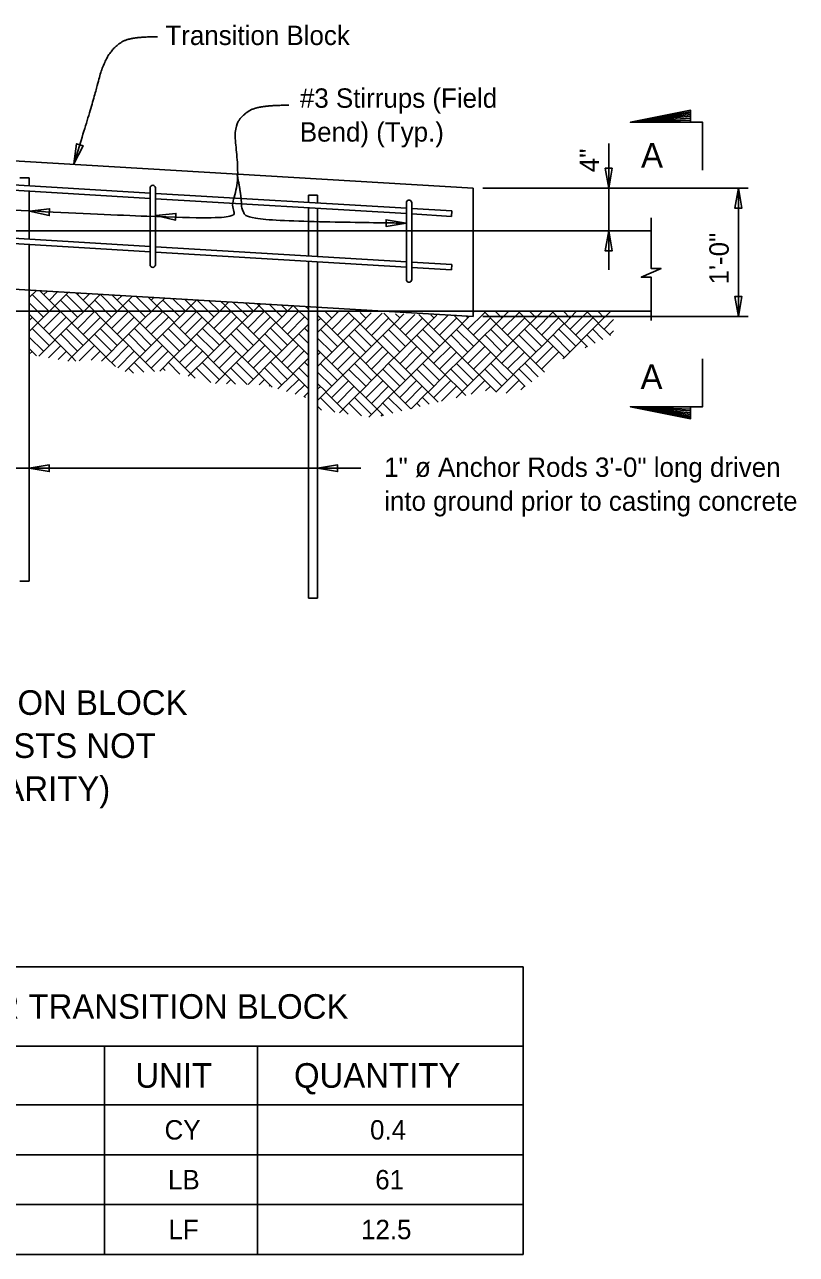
# Model space of a CAD drawing. Extents: x 0 to 120, y 0 to 45.
# Drawn here: x 20.88 to 32.92, y 4.99 to 24.18 of the extents above; entities that cross this region are included whole.
import ezdxf

# ---------------------------------------------------------------- set-up
doc = ezdxf.new("R2010")
doc.units = 0
for name, color, linetype in [('AdhocPoint_dp', 7, 'Continuous'), ('Miscellaneous', 7, 'Continuous'), ('PlotBorder_dp', 7, 'Continuous'), ('Rebar', 7, 'Continuous'), ('SubStrConc', 7, 'Continuous'), ('TextMisc', 7, 'Continuous'), ('TextStructures', 7, 'Continuous')]:
    doc.layers.add(name, color=color, linetype=linetype)

# ---------------------------------------------------------------- blocks, each defined once
blk = doc.blocks.new('Terminator-Arrow')
at = {"layer": 'PlotBorder_dp'}
blk.add_lwpolyline([(0, 0), (-0.00041, 0.000069), (-0.00041, -0.000069)], close=True, dxfattribs=at)

msp = doc.modelspace()

# ---------------------------------------------------------------- linework, layer by layer
at = {"layer": 'AdhocPoint_dp'}
for p, q in [((27.88, 20.963), (30.658, 20.963)), ((15.815, 19.713), (30.658, 19.713))]:
    msp.add_line(p, q, dxfattribs=at)
at = {"layer": 'Miscellaneous'}
for p, q in [((21.064, 20.035), (20.951, 19.922)), ((21.264, 19.705), (21.001, 19.968)), ((21.565, 20.005), (21.088, 19.528)), ((21.616, 19.526), (21.11, 20.032)), ((21.235, 20.025), (21.176, 19.966)), ((21.401, 20.015), (21.264, 19.878)), ((21.529, 19.97), (21.795, 19.705)), ((21.678, 19.999), (21.883, 19.793)), ((21.732, 19.995), (21.708, 19.972)), ((21.899, 19.985), (21.796, 19.883)), ((22.065, 19.976), (21.885, 19.795)), ((22.327, 19.707), (22.063, 19.97)), ((22.678, 19.528), (22.241, 19.965)), ((22.402, 19.955), (22.327, 19.88)), ((21.176, 19.616), (20.951, 19.841)), ((21.441, 19.882), (21.706, 19.616)), ((21.885, 19.791), (21.618, 19.525)), ((22.15, 19.53), (21.886, 19.793)), ((22.238, 19.618), (21.975, 19.882)), ((22.566, 19.946), (22.15, 19.53)), ((22.503, 19.883), (22.769, 19.618)), ((22.621, 19.942), (22.857, 19.707)), ((22.947, 19.793), (22.68, 19.526)), ((22.809, 19.931), (22.945, 19.795)), ((22.899, 19.926), (22.859, 19.885)), ((23.066, 19.916), (22.947, 19.797)), ((23.212, 19.532), (22.949, 19.795)), ((23.3, 19.62), (23.037, 19.883)), ((23.389, 19.708), (23.189, 19.909)), ((23.567, 19.886), (23.212, 19.532)), ((23.741, 19.53), (23.373, 19.898)), ((23.403, 19.896), (23.389, 19.882)), ((23.566, 19.885), (23.831, 19.62)), ((24.009, 19.795), (23.742, 19.528)), ((23.752, 19.875), (23.919, 19.708)), ((23.94, 19.864), (24.008, 19.797)), ((24.067, 19.856), (24.009, 19.798)), ((24.274, 19.533), (24.011, 19.797)), ((24.363, 19.622), (24.132, 19.852)), ((24.568, 19.827), (24.274, 19.533)), ((24.451, 19.71), (24.32, 19.841)), ((24.803, 19.532), (24.504, 19.83)), ((24.696, 19.819), (24.893, 19.622)), ((25.071, 19.797), (24.805, 19.53)), ((24.884, 19.808), (24.981, 19.71)), ((25.308, 19.564), (25.075, 19.796)), ((25.308, 19.74), (25.263, 19.785)), ((21.088, 19.528), (20.951, 19.664)), ((20.999, 19.613), (20.951, 19.565)), ((21.439, 19.703), (21.176, 19.44)), ((21.528, 19.615), (21.264, 19.351)), ((21.973, 19.703), (21.706, 19.436)), ((22.062, 19.615), (21.795, 19.348)), ((22.502, 19.705), (22.238, 19.441)), ((22.59, 19.616), (22.327, 19.353)), ((23.035, 19.705), (22.768, 19.438)), ((23.124, 19.616), (22.857, 19.35)), ((23.564, 19.707), (23.3, 19.443)), ((23.652, 19.618), (23.389, 19.355)), ((24.098, 19.707), (23.831, 19.44)), ((24.186, 19.618), (23.919, 19.351)), ((24.626, 19.708), (24.363, 19.445)), ((24.715, 19.62), (24.451, 19.357)), ((25.16, 19.708), (24.893, 19.441)), ((25.248, 19.62), (24.981, 19.353)), ((25.586, 19.513), (25.451, 19.648)), ((25.497, 19.598), (25.451, 19.552)), ((25.674, 19.602), (25.567, 19.709)), ((25.774, 19.702), (25.586, 19.513)), ((25.937, 19.688), (25.674, 19.425)), ((25.762, 19.69), (25.75, 19.703)), ((26.026, 19.6), (25.762, 19.337)), ((26.114, 19.512), (25.929, 19.696)), ((26.116, 19.69), (26.204, 19.602)), ((26.29, 19.684), (26.116, 19.51)), ((26.461, 19.678), (26.204, 19.422)), ((26.56, 19.6), (26.293, 19.333)), ((26.648, 19.515), (26.486, 19.677)), ((26.799, 19.667), (26.648, 19.515)), ((26.736, 19.604), (26.669, 19.671)), ((26.97, 19.661), (26.736, 19.427)), ((27.088, 19.602), (26.825, 19.338)), ((27.176, 19.513), (27.031, 19.659)), ((27.315, 19.649), (27.178, 19.512)), ((27.218, 19.652), (27.267, 19.604)), ((27.486, 19.643), (27.267, 19.423)), ((27.622, 19.602), (27.355, 19.335)), ((27.71, 19.517), (27.588, 19.639)), ((27.824, 19.631), (27.71, 19.517)), ((27.799, 19.605), (27.771, 19.633)), ((28.062, 19.692), (27.799, 19.429)), ((27.903, 19.709), (27.882, 19.689)), ((27.887, 19.694), (27.882, 19.699)), ((28.15, 19.604), (27.887, 19.34)), ((28.239, 19.515), (28.045, 19.709)), ((28.225, 19.709), (28.329, 19.605)), ((28.436, 19.709), (28.24, 19.514)), ((28.596, 19.692), (28.329, 19.425)), ((28.402, 19.709), (28.417, 19.694)), ((28.684, 19.604), (28.417, 19.337)), ((28.772, 19.519), (28.583, 19.709)), ((28.861, 19.607), (28.759, 19.709)), ((28.962, 19.708), (28.772, 19.519)), ((29.124, 19.694), (28.861, 19.43)), ((28.949, 19.696), (28.936, 19.708)), ((29.213, 19.605), (28.949, 19.342)), ((29.301, 19.517), (29.11, 19.708)), ((29.29, 19.708), (29.391, 19.607)), ((29.495, 19.708), (29.303, 19.515)), ((29.658, 19.694), (29.391, 19.427)), ((29.467, 19.708), (29.48, 19.696)), ((29.746, 19.605), (29.48, 19.339)), ((29.835, 19.521), (29.648, 19.708)), ((29.923, 19.609), (29.824, 19.708)), ((30.022, 19.707), (29.835, 19.521)), ((30.07, 19.579), (29.923, 19.432)), ((30.012, 19.697), (30.001, 19.707)), ((21.086, 19.526), (20.951, 19.392)), ((20.997, 19.438), (21.263, 19.173)), ((21.086, 19.526), (21.351, 19.261)), ((21.616, 19.526), (21.353, 19.263)), ((21.795, 19.175), (21.531, 19.438)), ((22.148, 19.528), (21.618, 18.998)), ((22.146, 18.996), (21.618, 19.525)), ((22.06, 19.44), (22.325, 19.175)), ((22.148, 19.528), (22.413, 19.263)), ((22.678, 19.528), (22.415, 19.265)), ((22.857, 19.176), (22.593, 19.44)), ((23.21, 19.53), (22.68, 19)), ((23.209, 18.998), (22.68, 19.526)), ((23.122, 19.441), (23.387, 19.176)), ((23.21, 19.53), (23.476, 19.265)), ((23.741, 19.53), (23.477, 19.266)), ((23.919, 19.178), (23.656, 19.441)), ((24.273, 19.532), (23.742, 19.001)), ((24.271, 19), (23.742, 19.528)), ((24.184, 19.443), (24.449, 19.178)), ((24.273, 19.532), (24.538, 19.266)), ((24.803, 19.532), (24.54, 19.268)), ((24.981, 19.18), (24.718, 19.443)), ((25.308, 19.026), (24.805, 19.53)), ((25.308, 19.507), (24.805, 19.003)), ((25.247, 19.445), (25.308, 19.383)), ((25.584, 19.512), (25.451, 19.379)), ((25.496, 19.423), (25.761, 19.158)), ((25.584, 19.512), (25.849, 19.247)), ((26.114, 19.512), (25.851, 19.248)), ((26.293, 19.16), (26.029, 19.423)), ((26.646, 19.514), (26.116, 18.983)), ((26.644, 18.981), (26.116, 19.51)), ((26.558, 19.425), (26.823, 19.16)), ((26.646, 19.514), (26.911, 19.248)), ((27.176, 19.513), (26.913, 19.25)), ((27.355, 19.162), (27.092, 19.425)), ((27.708, 19.515), (27.178, 18.985)), ((27.707, 18.983), (27.178, 19.512)), ((27.62, 19.427), (27.885, 19.162)), ((27.708, 19.515), (27.974, 19.25)), ((28.239, 19.515), (27.975, 19.252)), ((28.417, 19.163), (28.154, 19.427)), ((28.771, 19.517), (28.24, 18.987)), ((28.769, 18.985), (28.24, 19.514)), ((28.682, 19.429), (28.948, 19.163)), ((28.771, 19.517), (29.036, 19.252)), ((29.301, 19.517), (29.038, 19.254)), ((29.48, 19.165), (29.216, 19.429)), ((29.833, 19.519), (29.303, 18.988)), ((29.664, 19.154), (29.303, 19.515)), ((29.745, 19.43), (29.904, 19.271)), ((29.833, 19.519), (30.022, 19.329)), ((30.07, 19.402), (30.012, 19.344)), ((20.951, 19.307), (21.174, 19.084)), ((21.353, 19.259), (21.102, 19.008)), ((21.618, 18.998), (21.354, 19.261)), ((21.706, 19.086), (21.443, 19.35)), ((21.971, 19.351), (22.237, 19.086)), ((22.415, 19.261), (22.148, 18.994)), ((22.68, 19), (22.417, 19.263)), ((22.768, 19.088), (22.505, 19.351)), ((23.034, 19.353), (23.299, 19.088)), ((23.477, 19.263), (23.21, 18.996)), ((23.742, 19.001), (23.479, 19.265)), ((23.831, 19.09), (23.567, 19.353)), ((24.096, 19.355), (24.361, 19.09)), ((24.54, 19.265), (24.273, 18.998)), ((24.805, 19.003), (24.541, 19.266)), ((24.893, 19.091), (24.63, 19.355)), ((25.158, 19.357), (25.308, 19.207)), ((25.451, 19.291), (25.672, 19.07)), ((25.851, 19.245), (25.584, 18.978)), ((26.116, 18.983), (25.852, 19.247)), ((26.204, 19.072), (25.941, 19.335)), ((26.469, 19.337), (26.735, 19.072)), ((26.913, 19.247), (26.646, 18.98)), ((27.178, 18.985), (26.915, 19.248)), ((27.267, 19.073), (27.003, 19.337)), ((27.532, 19.339), (27.797, 19.073)), ((27.975, 19.248), (27.708, 18.981)), ((28.24, 18.987), (27.977, 19.25)), ((28.329, 19.075), (28.065, 19.339)), ((28.594, 19.34), (28.859, 19.075)), ((29.038, 19.25), (28.771, 18.983)), ((29.303, 18.988), (29.039, 19.252)), ((29.391, 19.077), (29.128, 19.34)), ((29.656, 19.342), (29.785, 19.213)), ((21.064, 19.015), (20.951, 19.127)), ((20.996, 19.083), (20.951, 19.038)), ((21.441, 19.171), (21.253, 18.983)), ((21.529, 19.083), (21.404, 18.958)), ((21.97, 19.173), (21.734, 18.937)), ((22.058, 19.084), (21.921, 18.947)), ((22.503, 19.173), (22.236, 18.906)), ((22.592, 19.084), (22.334, 18.827)), ((22.678, 18.998), (22.448, 18.767)), ((22.678, 18.998), (22.906, 18.77)), ((23.032, 19.175), (22.768, 18.911)), ((23.12, 19.086), (22.857, 18.823)), ((23.209, 18.998), (22.988, 18.777)), ((23.566, 19.175), (23.299, 18.908)), ((23.654, 19.086), (23.387, 18.819)), ((23.741, 19), (23.435, 18.694)), ((23.741, 19), (24.006, 18.734)), ((24.094, 19.176), (23.831, 18.913)), ((24.183, 19.088), (23.919, 18.825)), ((24.271, 19), (24.008, 18.736)), ((24.745, 18.525), (24.273, 18.998)), ((24.628, 19.176), (24.361, 18.909)), ((24.803, 19.001), (24.369, 18.568)), ((24.716, 19.088), (24.449, 18.821)), ((24.803, 19.001), (25.068, 18.736)), ((25.156, 19.178), (24.893, 18.915)), ((25.245, 19.09), (24.981, 18.826)), ((25.582, 18.98), (25.451, 19.11)), ((25.494, 19.068), (25.451, 19.026)), ((25.939, 19.156), (25.672, 18.89)), ((26.028, 19.068), (25.761, 18.801)), ((26.468, 19.158), (26.204, 18.895)), ((26.556, 19.07), (26.293, 18.806)), ((27.001, 19.158), (26.735, 18.891)), ((27.09, 19.07), (26.823, 18.803)), ((27.53, 19.16), (27.267, 18.897)), ((27.618, 19.072), (27.355, 18.808)), ((28.064, 19.16), (27.797, 18.893)), ((28.152, 19.072), (27.885, 18.805)), ((28.592, 19.162), (28.329, 18.898)), ((28.681, 19.073), (28.417, 18.81)), ((29.126, 19.162), (28.859, 18.895)), ((29.214, 19.073), (28.947, 18.806)), ((29.655, 19.163), (29.627, 19.136)), ((21.616, 18.996), (21.553, 18.933)), ((21.616, 18.996), (21.681, 18.931)), ((22.146, 18.996), (22.082, 18.931)), ((22.296, 18.847), (22.148, 18.994)), ((22.502, 18.821), (22.579, 18.743)), ((22.59, 18.909), (22.743, 18.757)), ((23.073, 18.784), (23.035, 18.821)), ((23.304, 18.729), (23.124, 18.909)), ((23.541, 18.665), (23.21, 18.996)), ((23.564, 18.823), (23.788, 18.599)), ((23.652, 18.911), (23.917, 18.646)), ((24.352, 18.568), (24.098, 18.823)), ((24.449, 18.648), (24.186, 18.911)), ((24.626, 18.825), (24.891, 18.559)), ((24.715, 18.913), (24.98, 18.648)), ((25.308, 18.976), (25.07, 18.738)), ((25.308, 18.676), (25.16, 18.825)), ((25.308, 18.853), (25.248, 18.913)), ((25.582, 18.98), (25.451, 18.849)), ((25.761, 18.628), (25.497, 18.891)), ((26.114, 18.981), (25.584, 18.451)), ((26.112, 18.449), (25.584, 18.978)), ((25.937, 18.805), (26.203, 18.54)), ((26.026, 18.893), (26.291, 18.628)), ((26.114, 18.981), (26.379, 18.716)), ((26.644, 18.981), (26.381, 18.718)), ((26.735, 18.541), (26.471, 18.805)), ((26.823, 18.63), (26.56, 18.893)), ((27.176, 18.983), (26.646, 18.453)), ((27.175, 18.451), (26.646, 18.98)), ((27, 18.806), (27.265, 18.541)), ((27.088, 18.895), (27.353, 18.63)), ((27.176, 18.983), (27.442, 18.718)), ((27.707, 18.983), (27.443, 18.72)), ((27.797, 18.543), (27.533, 18.806)), ((27.885, 18.631), (27.622, 18.895)), ((28.239, 18.985), (27.708, 18.455)), ((28.237, 18.453), (27.708, 18.981)), ((28.062, 18.808), (28.327, 18.543)), ((28.15, 18.897), (28.416, 18.631)), ((28.239, 18.985), (28.504, 18.72)), ((28.769, 18.985), (28.506, 18.722)), ((28.794, 18.61), (28.596, 18.808)), ((28.895, 18.686), (28.684, 18.897)), ((28.994, 18.76), (28.771, 18.983)), ((29.301, 18.987), (29.281, 18.967)), ((29.301, 18.987), (29.308, 18.98)), ((24.008, 18.733), (23.858, 18.584)), ((24.17, 18.574), (24.009, 18.734)), ((24.096, 18.644), (24.03, 18.578)), ((24.624, 18.646), (24.541, 18.563)), ((25.07, 18.734), (24.833, 18.498)), ((25.158, 18.646), (24.968, 18.456)), ((25.308, 18.5), (25.071, 18.736)), ((25.672, 18.54), (25.451, 18.76)), ((25.936, 18.626), (25.672, 18.363)), ((26.381, 18.715), (26.114, 18.448)), ((26.469, 18.626), (26.203, 18.359)), ((26.646, 18.453), (26.383, 18.716)), ((26.998, 18.628), (26.735, 18.365)), ((27.443, 18.716), (27.176, 18.449)), ((27.532, 18.628), (27.265, 18.361)), ((27.708, 18.455), (27.445, 18.718)), ((28.06, 18.63), (27.848, 18.418)), ((28.506, 18.718), (28.239, 18.451)), ((28.594, 18.63), (28.396, 18.432)), ((28.693, 18.534), (28.507, 18.72)), ((24.713, 18.558), (24.696, 18.541)), ((25.247, 18.558), (25.103, 18.414)), ((25.308, 18.446), (25.235, 18.373)), ((25.584, 18.451), (25.451, 18.584)), ((25.496, 18.536), (25.451, 18.492)), ((25.582, 18.449), (25.451, 18.319)), ((25.582, 18.449), (25.847, 18.184)), ((26.024, 18.538), (25.761, 18.274)), ((26.112, 18.449), (25.849, 18.186)), ((26.479, 18.082), (26.114, 18.448)), ((26.644, 18.451), (26.251, 18.058)), ((26.558, 18.538), (26.291, 18.271)), ((26.644, 18.451), (26.908, 18.187)), ((27.086, 18.54), (26.823, 18.276)), ((27.175, 18.451), (26.912, 18.188)), ((27.334, 18.292), (27.176, 18.449)), ((27.62, 18.54), (27.385, 18.304)), ((27.707, 18.453), (27.614, 18.36)), ((27.707, 18.453), (27.763, 18.397)), ((28.149, 18.541), (28.073, 18.466)), ((28.237, 18.453), (28.233, 18.449)), ((28.242, 18.448), (28.239, 18.451)), ((28.682, 18.541), (28.624, 18.483)), ((25.245, 18.383), (25.263, 18.364)), ((25.494, 18.361), (25.719, 18.136)), ((26.137, 18.075), (25.939, 18.273)), ((26.291, 18.098), (26.028, 18.361)), ((26.468, 18.274), (26.624, 18.118)), ((26.556, 18.363), (26.766, 18.153)), ((27.053, 18.223), (27.001, 18.274)), ((27.195, 18.258), (27.09, 18.363)), ((27.618, 18.365), (27.621, 18.362)), ((25.451, 18.227), (25.511, 18.167)), ((25.849, 18.183), (25.792, 18.125)), ((25.93, 18.105), (25.851, 18.184)), ((26.466, 18.096), (26.444, 18.074))]:
    msp.add_line(p, q, dxfattribs=at)
at = {"layer": 'PlotBorder_dp'}
for p, q in [((29.995, 22.328), (29.995, 20.358)), ((28.031, 21.629), (32.17, 21.629)), ((28.031, 21.629), (30.146, 21.629)), ((32.019, 21.629), (32.019, 19.629)), ((28.031, 19.629), (32.17, 19.629)), ((26.127, 17.26), (16.451, 17.26))]:
    msp.add_line(p, q, dxfattribs=at)
for points in [[(21.65, 22.009), (21.793, 22.291), (21.691, 22.323)], [(20.956, 21.272), (21.265, 21.203), (21.271, 21.308)], [(22.926, 21.201), (23.235, 21.131), (23.241, 21.237)], [(26.832, 21.085), (26.52, 21.138), (26.52, 21.032)], [(20.951, 17.26), (21.264, 17.207), (21.264, 17.313)], [(25.451, 17.26), (25.764, 17.207), (25.764, 17.313)]]:
    msp.add_lwpolyline(points, close=True, dxfattribs=at)
msp.add_lwpolyline([(30.658, 19.567), (30.658, 20.241), (30.503, 20.241), (30.658, 20.308), (30.813, 20.376), (30.658, 20.376), (30.658, 21.166)], dxfattribs=at)
for points in [[(22.956, 23.992), (22.617, 23.992), (22.327, 23.895), (22.101, 23.581), (21.98, 23.081), (21.65, 22.009)], [(25.003, 22.924), (24.543, 22.924), (24.269, 22.77), (24.14, 22.537), (24.229, 21.9), (24.124, 21.279), (24.036, 21.101), (18.926, 21.376)], [(24.195, 21.849), (24.263, 21.511), (24.263, 21.277), (24.408, 21.128), (26.566, 21.085), (26.832, 21.085)]]:
    msp.add_open_spline(points, degree=2, dxfattribs=at)
at = {"layer": 'Rebar'}
for p, q in [((18.922, 21.787), (22.838, 21.554)), ((18.922, 21.703), (22.838, 21.47)), ((20.808, 21.791), (20.951, 21.791)), ((20.951, 21.791), (20.951, 21.666)), ((20.951, 21.583), (20.951, 20.833)), ((22.838, 20.435), (22.838, 21.634)), ((22.922, 20.435), (22.922, 21.634)), ((22.922, 21.549), (26.838, 21.316)), ((25.308, 21.523), (25.308, 21.407)), ((25.308, 21.523), (25.451, 21.523)), ((25.451, 21.523), (25.451, 21.398)), ((22.922, 21.465), (26.838, 21.232)), ((25.308, 21.323), (25.308, 20.573)), ((25.451, 21.315), (25.451, 20.565)), ((26.838, 20.203), (26.838, 21.402)), ((26.921, 20.203), (26.921, 21.402)), ((26.921, 21.311), (27.546, 21.274)), ((26.921, 21.227), (27.541, 21.19)), ((27.546, 21.274), (27.541, 21.19)), ((18.922, 20.954), (22.838, 20.72)), ((18.922, 20.87), (22.838, 20.637)), ((20.951, 20.749), (20.951, 15.499)), ((22.922, 20.715), (26.838, 20.482)), ((22.922, 20.632), (26.838, 20.399)), ((25.308, 20.49), (25.308, 15.231)), ((25.451, 20.481), (25.451, 15.231)), ((26.921, 20.477), (27.546, 20.44)), ((26.921, 20.394), (27.541, 20.357)), ((27.546, 20.44), (27.541, 20.357)), ((20.951, 15.499), (20.808, 15.499)), ((25.451, 15.231), (25.308, 15.231))]:
    msp.add_line(p, q, dxfattribs=at)
for centre, start, end in [((22.88, 21.634), 0, 180), ((26.88, 21.402), 0, 180), ((22.88, 20.435), 180, 0), ((26.88, 20.203), 180, 0)]:
    msp.add_arc(centre, 0.0417, start, end, dxfattribs=at)
at = {"layer": 'SubStrConc'}
for p, q in [((27.88, 21.629), (13.88, 22.463)), ((27.88, 19.629), (27.88, 21.629)), ((15.806, 20.963), (27.88, 20.963)), ((27.88, 19.629), (13.88, 20.463))]:
    msp.add_line(p, q, dxfattribs=at)
at = {"layer": 'TextMisc'}
for p, q in [((30.334, 22.658), (31.272, 22.823)), ((31.272, 22.803), (30.334, 22.658)), ((30.334, 22.658), (31.272, 22.778)), ((31.272, 22.751), (30.334, 22.658)), ((30.334, 22.658), (31.272, 22.723)), ((31.272, 22.693), (30.334, 22.658)), ((31.272, 18.183), (30.334, 18.218)), ((30.334, 18.218), (31.272, 18.153)), ((31.272, 18.126), (30.334, 18.218)), ((30.334, 18.218), (31.272, 18.098)), ((31.272, 18.073), (30.334, 18.218)), ((30.334, 18.218), (31.272, 18.053)), ((13.197, 9.48), (28.661, 9.48)), ((28.661, 4.994), (28.661, 9.48)), ((13.197, 8.245), (28.661, 8.245)), ((22.127, 4.994), (22.127, 8.245)), ((24.514, 4.994), (24.514, 8.245)), ((13.197, 7.326), (28.661, 7.326)), ((13.197, 4.994), (28.661, 4.994))]:
    msp.add_line(p, q, dxfattribs=at)
for points in [[(31.459, 21.908), (31.459, 22.658), (30.334, 22.658), (31.272, 22.846), (31.272, 22.658)], [(31.459, 18.968), (31.459, 18.218), (30.334, 18.218), (31.272, 18.031), (31.272, 18.218)]]:
    msp.add_lwpolyline(points, dxfattribs=at)
at = {"layer": 'TextStructures'}
for p, q in [((13.197, 6.549), (28.661, 6.549)), ((13.197, 5.771), (28.661, 5.771))]:
    msp.add_line(p, q, dxfattribs=at)

# ---------------------------------------------------------------- block references
at = {"layer": 'PlotBorder_dp', "xscale": 759.4584810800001, "yscale": 768.046082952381}
for p, rotation in [((29.995, 21.629), -90), ((32.019, 21.629), 90), ((29.995, 20.963), 90), ((32.019, 19.629), -90)]:
    msp.add_blockref('Terminator-Arrow', p, dxfattribs=dict(at, rotation=rotation))

# ---------------------------------------------------------------- texts
at = {"layer": 'TextStructures'}
for s, height, p in [('Transition Block', 0.3024, (23.078, 23.863)), ('#3 Stirrups (Field ', 0.3024, (25.176, 22.884)), ('Bend) (Typ.)', 0.3024, (25.176, 22.356)), ('A', 0.384, (30.5, 21.952)), ('A', 0.384, (30.492, 18.495)), ('1" ø Anchor Rods 3\'-0" long driven ', 0.3024, (26.491, 17.125)), ('into ground prior to casting concrete', 0.3024, (26.491, 16.597)), ('ELEVATION OF TRANSITION BLOCK', 0.384, (14.549, 13.412)), ('(GUARDRAIL AND POSTS NOT', 0.384, (15.424, 12.74)), ('SHOWN FOR CLARITY)', 0.384, (16.539, 12.068)), ('ESTIMATED QUANTITIES PER TRANSITION BLOCK', 0.384, (13.437, 8.67)), ('UNIT', 0.384, (22.608, 7.594)), ('QUANTITY', 0.384, (25.084, 7.594)), ('CY', 0.3024, (23.064, 6.786)), ('0.4', 0.3024, (26.271, 6.786)), ('LB', 0.3024, (23.118, 6.009)), ('61', 0.3024, (26.352, 6.009)), ('LF', 0.3024, (23.126, 5.231)), ('12.5', 0.3024, (26.13, 5.231))]:
    msp.add_text(s, height=height, dxfattribs=at).set_placement(p)
for s, p in [('4"', (29.844, 21.879)), ('1\'-0"', (31.868, 20.129))]:
    msp.add_text(s, height=0.3024, rotation=90, dxfattribs=at).set_placement(p)

doc.saveas('drawing.dxf')
